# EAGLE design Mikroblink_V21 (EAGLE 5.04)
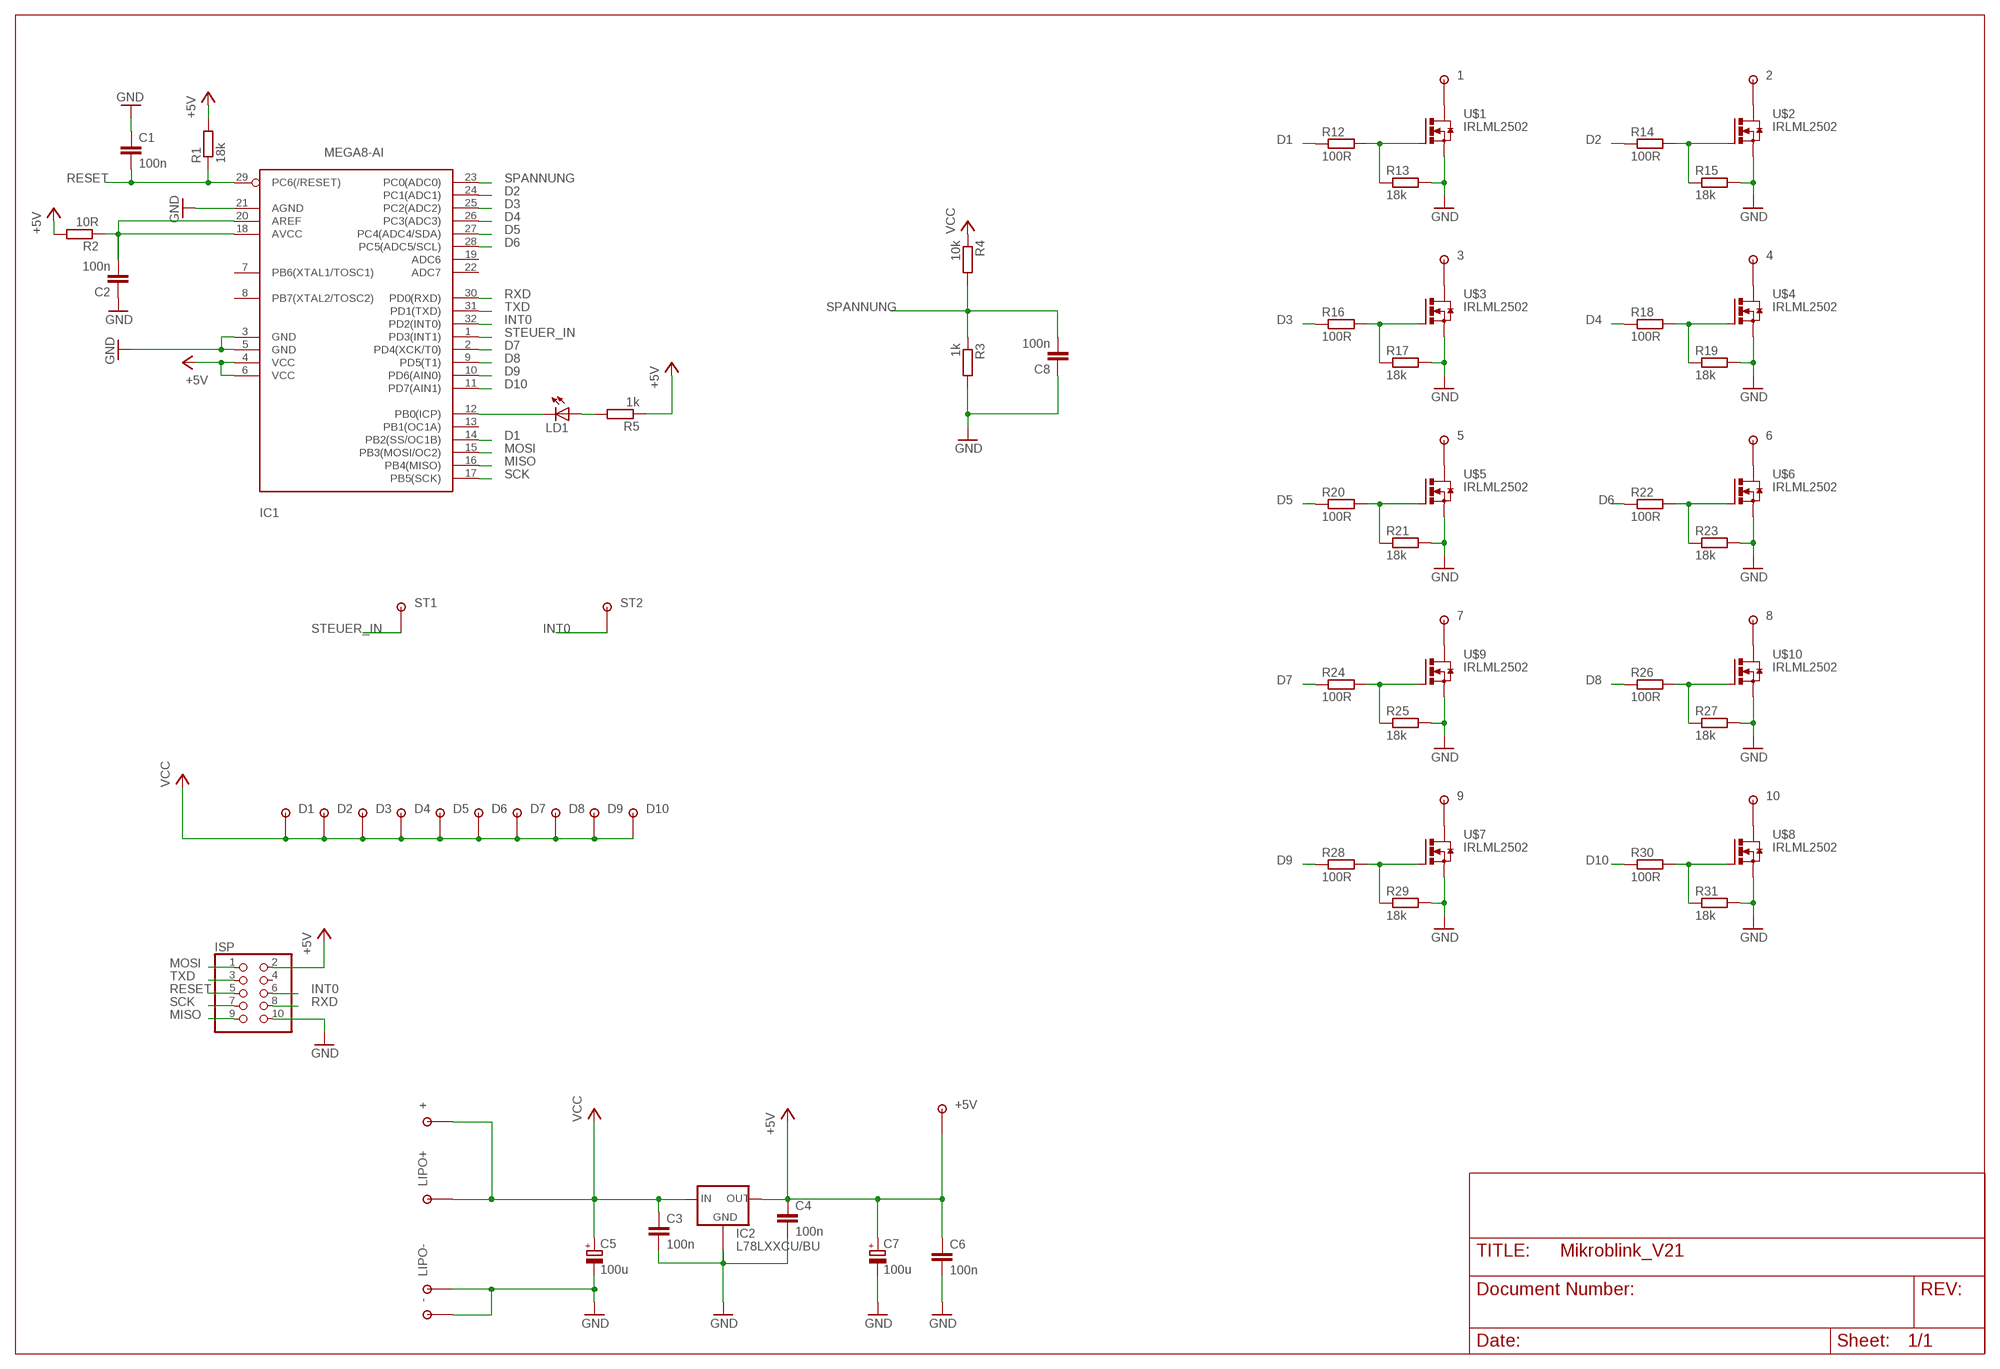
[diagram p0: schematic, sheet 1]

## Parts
1  PAD1  [PAD1]
2  PAD1  [PAD1]
3  PAD1  [PAD1]
4  PAD1  [PAD1]
5  PAD1  [PAD1]
6  PAD1  [PAD1]
7  PAD1  [PAD1]
8  PAD1  [PAD1]
9  PAD1  [PAD1]
10  PAD1  [PAD1]
+  PAD1  [PAD1]
+5V  PAD1  [PAD1]
-  PAD1  [PAD1]
C1  100n  C-EUC0805  [C0805]
C2  100n  C-EUC0805  [C0805]
C3  100n  C-EUC0805  [C0805]
C4  100n  C-EUC0805  [C0805]
C5  100u  CPOL-EU153CLV-0405  [153CLV-0405]
C6  100n  C-EUC0805  [C0805]
C7  100u  CPOL-EU153CLV-0405  [153CLV-0405]
C8  100n  C-EUC0805  [C0805]
D1  PAD1  [PAD1]
D2  PAD1  [PAD1]
D3  PAD1  [PAD1]
D4  PAD1  [PAD1]
D5  PAD1  [PAD1]
D6  PAD1  [PAD1]
D7  PAD1  [PAD1]
D8  PAD1  [PAD1]
D9  PAD1  [PAD1]
D10  PAD1  [PAD1]
IC1  MEGA8-AI  [TQFP32-08]
IC2  L78LXXCU/BU  [SOT89]
ISP  ISP_RAINER  [ISP_RAINER]
LD1  LEDCHIP-LED0805  [CHIP-LED0805]
LIPO+  PAD1  [PAD1]
LIPO-  PAD1  [PAD1]
R1  18k  R-EU_R0805  [R0805]
R2  10R  R-EU_R0805  [R0805]
R3  1k  R-EU_R0805  [R0805]
R4  10k  R-EU_R0805  [R0805]
R5  1k  R-EU_R0805  [R0805]
R12  100R  R-EU_R0805  [R0805]
R13  18k  R-EU_R0805  [R0805]
R14  100R  R-EU_R0805  [R0805]
R15  18k  R-EU_R0805  [R0805]
R16  100R  R-EU_R0805  [R0805]
R17  18k  R-EU_R0805  [R0805]
R18  100R  R-EU_R0805  [R0805]
R19  18k  R-EU_R0805  [R0805]
R20  100R  R-EU_R0805  [R0805]
R21  18k  R-EU_R0805  [R0805]
R22  100R  R-EU_R0805  [R0805]
R23  18k  R-EU_R0805  [R0805]
R24  100R  R-EU_R0805  [R0805]
R25  18k  R-EU_R0805  [R0805]
R26  100R  R-EU_R0805  [R0805]
R27  18k  R-EU_R0805  [R0805]
R28  100R  R-EU_R0805  [R0805]
R29  18k  R-EU_R0805  [R0805]
R30  100R  R-EU_R0805  [R0805]
R31  18k  R-EU_R0805  [R0805]
ST1  PAD1  [PAD1]
ST2  PAD1  [PAD1]
U$1  IRLML2502  [MICRO3]
U$2  IRLML2502  [MICRO3]
U$3  IRLML2502  [MICRO3]
U$4  IRLML2502  [MICRO3]
U$5  IRLML2502  [MICRO3]
U$6  IRLML2502  [MICRO3]
U$7  IRLML2502  [MICRO3]
U$8  IRLML2502  [MICRO3]
U$9  IRLML2502  [MICRO3]
U$10  IRLML2502  [MICRO3]

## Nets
+5V: +5V.P$1(PIN1) C4.1 C6.1 C7.+ IC1.4(VCC) IC1.6(VCC) IC2.1(OUT) ISP.2 R1.2 R2.2 R5.1
AREF_AVCC: C2.2 IC1.18(AVCC) IC1.20(AREF) R2.1
D1: IC1.14(PB2(SS/OC1B)) R12.1
D2: IC1.24(PC1(ADC1)) R14.1
D3: IC1.25(PC2(ADC2)) R16.1
D4: IC1.26(PC3(ADC3)) R18.1
D5: IC1.27(PC4(ADC4/SDA)) R20.1
D6: IC1.28(PC5(ADC5/SCL)) R22.1
D7: IC1.2(PD4(XCK/T0)) R24.1
D8: IC1.9(PD5(T1)) R26.1
D9: IC1.10(PD6(AIN0)) R28.1
D10: IC1.11(PD7(AIN1)) R30.1
GND: -.P$1(PIN1) C1.1 C2.1 C3.2 C4.2 C5.- C6.2 C7.- C8.1 IC1.3(GND) IC1.5(GND) IC1.21(AGND) IC2.4(GND1) ISP.10 LIPO-.P$1(PIN1) R3.2 R13.2 R15.2 R17.2 R19.2 R21.2 R23.2 R25.2 R27.2 R29.2 R31.2 U$1.2(S) U$2.2(S) U$3.2(S) U$4.2(S) U$5.2(S) U$6.2(S) U$7.2(S) U$8.2(S) U$9.2(S) U$10.2(S)
INT0: IC1.32(PD2(INT0)) ISP.6 ST2.P$1(PIN1)
MISO: IC1.16(PB4(MISO)) ISP.9
MOSI: IC1.15(PB3(MOSI/OC2)) ISP.1
N$1: R12.2 R13.1 U$1.1(G)
N$2: R14.2 R15.1 U$2.1(G)
N$3: R16.2 R17.1 U$3.1(G)
N$4: R18.2 R19.1 U$4.1(G)
N$5: R20.2 R21.1 U$5.1(G)
N$6: R22.2 R23.1 U$6.1(G)
N$7: R28.2 R29.1 U$7.1(G)
N$10: IC1.12(PB0(ICP)) LD1.C
N$12: LD1.A R5.2
N$13: R24.2 R25.1 U$9.1(G)
N$14: R26.2 R27.1 U$10.1(G)
N$16: R30.2 R31.1 U$8.1(G)
N$22: 1.P$1(PIN1) U$1.3(D)
N$23: 2.P$1(PIN1) U$2.3(D)
N$24: 3.P$1(PIN1) U$3.3(D)
N$25: 4.P$1(PIN1) U$4.3(D)
N$26: 5.P$1(PIN1) U$5.3(D)
N$27: 6.P$1(PIN1) U$6.3(D)
N$28: 7.P$1(PIN1) U$9.3(D)
N$29: 8.P$1(PIN1) U$10.3(D)
N$30: 9.P$1(PIN1) U$7.3(D)
N$31: 10.P$1(PIN1) U$8.3(D)
RESET: C1.2 IC1.29(PC6(/RESET)) ISP.5 R1.1
RXD: IC1.30(PD0(RXD)) ISP.8
SCK: IC1.17(PB5(SCK)) ISP.7
SPANNUNG: C8.2 IC1.23(PC0(ADC0)) R3.1 R4.2
STEUER_IN: IC1.1(PD3(INT1)) ST1.P$1(PIN1)
TXD: IC1.31(PD1(TXD)) ISP.3
VCC: +.P$1(PIN1) C3.1 C5.+ D1.P$1(PIN1) D2.P$1(PIN1) D3.P$1(PIN1) D4.P$1(PIN1) D5.P$1(PIN1) D6.P$1(PIN1) D7.P$1(PIN1) D8.P$1(PIN1) D9.P$1(PIN1) D10.P$1(PIN1) IC2.3(IN) LIPO+.P$1(PIN1) R4.1
Unconnected: IC1.7(PB6(XTAL1/TOSC1)) IC1.8(PB7(XTAL2/TOSC2)) IC1.13(PB1(OC1A)) IC1.19(ADC6) IC1.22(ADC7) IC2.2(GND) ISP.4

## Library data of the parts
1-10 + +5V - D1-D10 LIPO+ LIPO- ST1 ST2 = Rainer:PAD1
C1-C4 C6 C8 = rcl:C-EU: CAPACITOR, European symbol
C5 C7 = rcl:CPOL-EU: POLARIZED CAPACITOR, European symbol
IC1 = atmel:MEGA8: MICROCONTROLLER 8 Kbytes FLASH, 1 kbytes SRAM, 512 bytes EEPROM, USART, 6-channel 10 bit ADC, 2-channel 8 bit ADC Pin compatible with Atmega48, ATMega88, ATMega168 Source: avr.lbr
IC2 = v-reg:L78LXXCU/BU: VOLTAGE REGULATOR
ISP = pinhead:ISP_RAINER
LD1 = led:LED: LED
R1-R5 R12-R31 = rcl:R-EU_: RESISTOR, European symbol
U$1-U$10 = transistor-power:IRLML2502

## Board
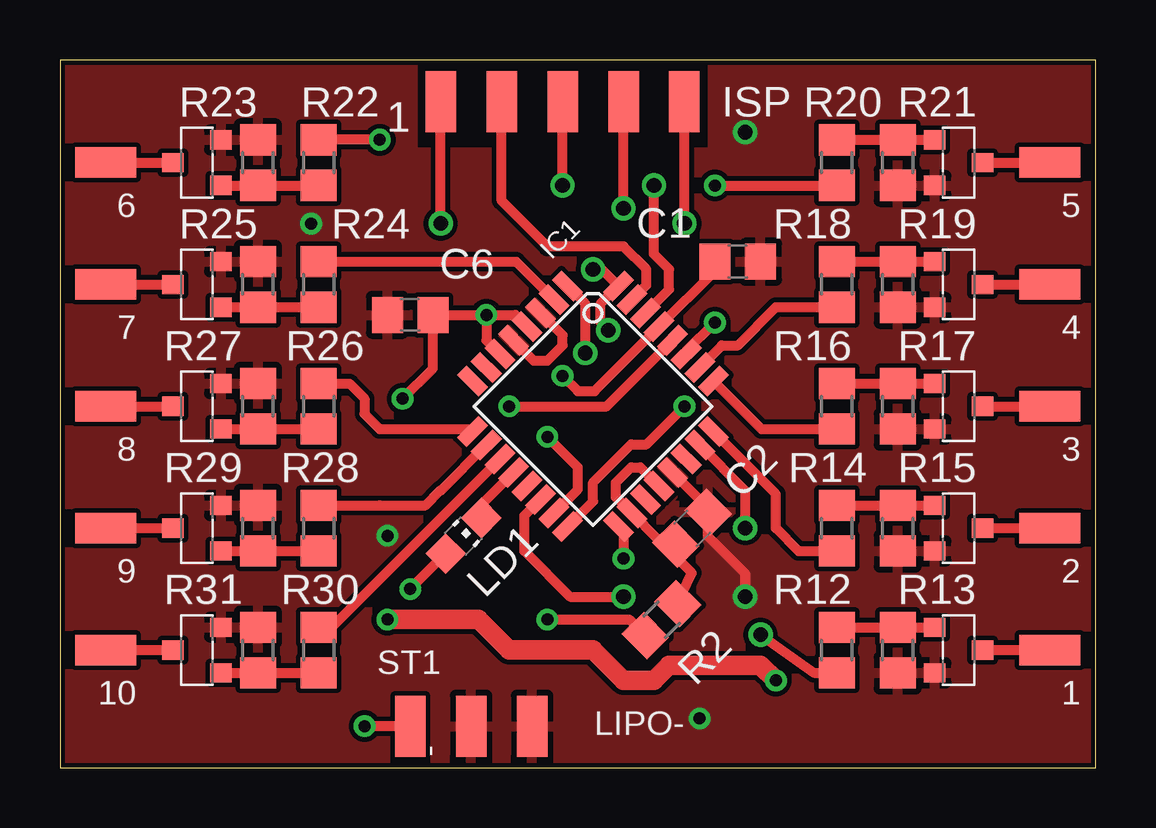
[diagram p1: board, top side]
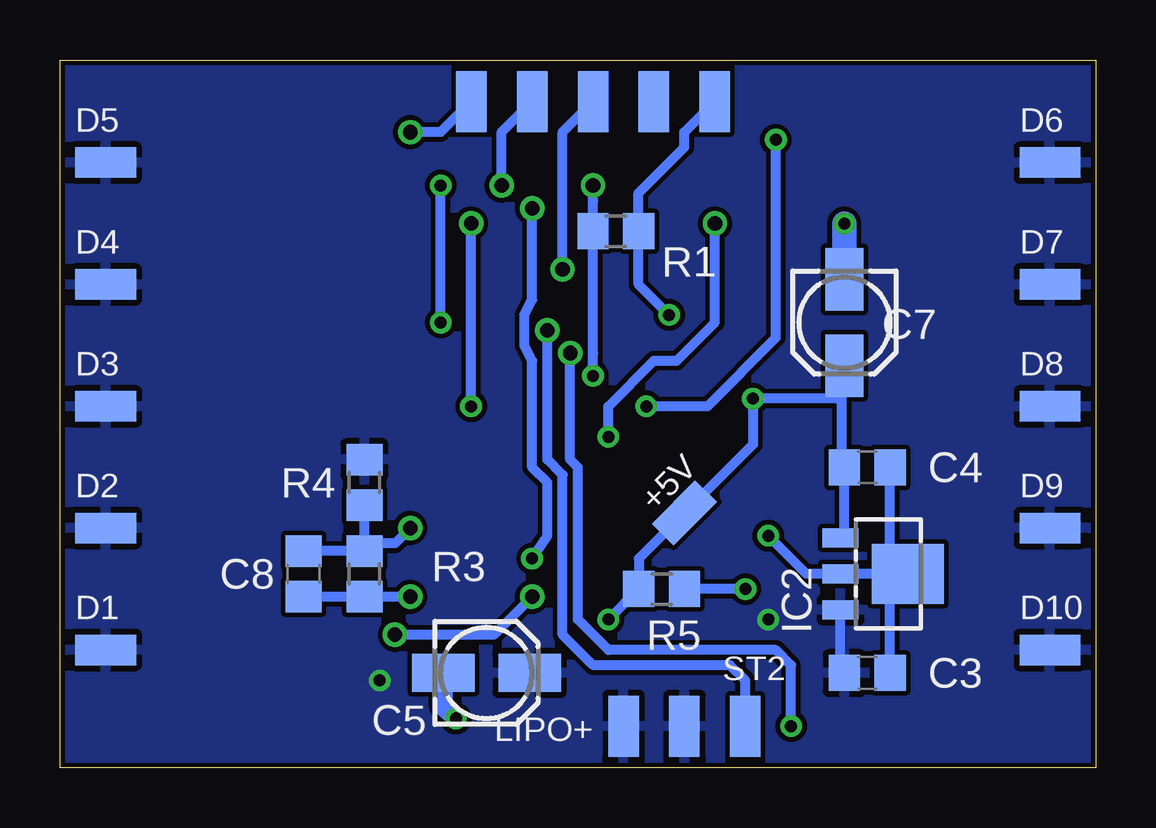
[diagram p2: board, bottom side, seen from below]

Size 43.17 x 29.52 mm. Coordinates in mm from the lower left corner, seen from the top.
Outline: 43.17,0 43.17,29.52 0,29.52 0,0 43.17,0
Copper layers (1*16): Top 0.035mm / dielectric 1.5mm / Bottom 0.035mm
Design rules "ZWILLING": minimum track width 0.2mm, minimum drill 0.5mm, track to track 0.2mm, track to pad 0.2mm, pad to pad 0.2mm, via to via 0.2mm, smd to smd 0mil, copper to edge 0.2mm, drill to drill 0.2mm, minimum pad ring 8mil, minimum via ring 8mil, stop-mask expansion 0.1mm, vias tented up to drill 0mil, thermal gap 10mil
tRestrict: area 14.9,25.9 to 27,29.4; area 17.7,10.6 to 26.7,19.6

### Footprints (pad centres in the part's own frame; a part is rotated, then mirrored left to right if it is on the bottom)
PAD1 = smd 2.54 x 1.27: P$1 0,0
C0805 = smd 1.3 x 1.5: 1 -0.95,0; 2 0.95,0
153CLV-0405 = smd 2.6 x 1.6: + 1.8,0; - -1.8,0
TQFP32-08 = smd 1.27 x 0.559: 1 -4.293,2.8; 2 -4.293,2; 3 -4.293,1.2; 4 -4.293,0.4; 5 -4.293,-0.4; 6 -4.293,-1.2; 7 -4.293,-2; 8 -4.293,-2.8; 17 4.293,-2.8; 18 4.293,-2; 19 4.293,-1.2; 20 4.293,-0.4; 21 4.293,0.4; 22 4.293,1.2; 23 4.293,2; 24 4.293,2.8 | smd 0.559 x 1.27: 9 -2.8,-4.293; 10 -2,-4.293; 11 -1.2,-4.293; 12 -0.4,-4.293; 13 0.4,-4.293; 14 1.2,-4.293; 15 2,-4.293; 16 2.8,-4.293; 25 2.8,4.293; 26 2,4.293; 27 1.2,4.293; 28 0.4,4.293; 29 -0.4,4.293; 30 -1.2,4.293; 31 -2,4.293; 32 -2.8,4.293
SOT89 = smd 0.8 x 1.5: 1 -1.5,-1.75; 2 0,-1.75; 3 1.5,-1.75 | smd 2.5 x 3: 4 0,1.05
ISP_RAINER = smd 2.54 x 1.27: 1 0,10.16; 3 0,7.62; 5 0,5.08; 7 0,2.54; 9 0,0 | smd 2.54 x 1.27 bottom: 2 0,10.16; 4 0,7.62; 6 0,5.08; 8 0,2.54; 10 0,0
CHIP-LED0805 = smd 1.2 x 1.2: A 0,-1.05; C 0,1.05
R0805 = smd 1.3 x 1.5: 1 -0.95,0; 2 0.95,0
MICRO3 = smd 0.8 x 0.9: 1 -0.95,-1; 2 0.95,-1; 3 0,1

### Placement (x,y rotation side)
1  41.27,4.92 180 top
2  41.27,10 180 top
3  41.27,15.07 180 top
4  41.27,20.16 180 top
5  41.27,25.23 180 top
6  1.9,25.23 180 top
7  1.9,20.16 180 top
8  1.9,15.07 180 top
9  1.9,10 180 top
10  1.9,4.92 180 top
+  17.14,1.74 270 bottom
+5V  17.14,10.63 225 bottom
-  17.14,1.74 90 top
C1  28.25,21.11 180 top
C2  26.35,10 225 top
C3  9.52,3.96 0 bottom
C4  9.52,12.54 0 bottom
C5  25.39,3.96 0 bottom
C6  14.6,18.89 180 top
C7  10.47,18.57 270 bottom
C8  33.02,8.09 90 bottom
D1  41.27,4.92 0 bottom
D2  41.27,10 0 bottom
D3  41.27,15.07 0 bottom
D4  41.27,20.16 0 bottom
D5  41.27,25.23 0 bottom
D6  1.9,25.23 0 bottom
D7  1.9,20.16 0 bottom
D8  1.9,15.07 0 bottom
D9  1.9,10 0 bottom
D10  1.9,4.92 0 bottom
IC1  22.22,15.07 315 top
IC2  8.88,8.09 270 bottom
ISP  26.03,27.77 90 top
LD1  16.82,9.68 315 top
LIPO+  19.68,1.74 90 bottom
LIPO-  19.68,1.74 90 top
R1  20,22.38 0 bottom
R2  25.08,6.18 225 top
R3  30.48,8.09 270 bottom
R4  30.48,11.9 270 bottom
R5  18.09,7.45 0 bottom
R12  32.38,4.92 90 top
R13  34.92,4.92 270 top
R14  32.38,10 90 top
R15  34.92,10 270 top
R16  32.38,15.07 90 top
R17  34.92,15.07 270 top
R18  32.38,20.16 90 top
R19  34.92,20.16 270 top
R20  32.38,25.23 90 top
R21  34.92,25.23 270 top
R22  10.79,25.23 270 top
R23  8.25,25.23 90 top
R24  10.79,20.16 270 top
R25  8.25,20.16 90 top
R26  10.79,15.07 270 top
R27  8.25,15.07 90 top
R28  10.79,10 270 top
R29  8.25,10 90 top
R30  10.79,4.92 270 top
R31  8.25,4.92 90 top
ST1  14.6,1.74 90 top
ST2  14.6,1.74 90 bottom
U$1  37.46,4.92 270 top
U$2  37.46,10 270 top
U$3  37.46,15.07 270 top
U$4  37.46,20.16 270 top
U$5  37.46,25.23 270 top
U$6  5.71,25.23 90 top
U$7  5.71,10 90 top
U$8  5.71,4.92 90 top
U$9  5.71,20.16 90 top
U$10  5.71,15.07 90 top

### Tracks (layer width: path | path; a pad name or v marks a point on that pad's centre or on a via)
+5V  (via drill 0.5)
  Top 0.406: v17.78,18.89 C6.1 15.55,16.66 v14.28,15.39 | IC1.4 18.98,18.89 v17.78,18.89 | IC1.6 17.78,17.82 v17.78,18.89 | v20.32,6.18 23.73,6.18 R2.2
  Bottom 0.406: v17.78,18.89 19.05,20.16 R1.2 19.05,23.96 17.14,25.87 17.14,26.5 ISP.2 | 10.58,15.39 v14.28,15.39 14.28,13.49 +5V.P$1 19.04,8.73 R5.1 v20.32,6.18 | 10.58,15.39 C7.+ | 10.58,15.39 10.58,12.64 C4.1 10.47,9.75 IC2.1
AREF_AVCC
  Top 0.406: C2.2 25.14,9.32 24.93,9.53 | 24.93,9.53 IC1.18 23.17,11.29 23.17,11.9 23.81,12.54 24.19,12.54 IC1.20 | R2.1 26.34,8.13 24.93,9.53
D1  (via drill 0.61)
  Top 0.406: IC1.14 19.36,10.52 19.36,9.04 21.27,7.14 v23.49,7.14 | R12.1 31.43,3.96 v29.21,5.55
  Bottom 0.406: v29.21,5.55 25.08,5.55 v23.49,7.14
D2
  Top 0.406: R14.1 30.79,9.04 29.84,10 29.84,11.41 IC1.24
D3
  Top 0.406: IC1.25 29.24,14.12 R16.1
D4
  Top 0.406: 31.72,19.21 R18.1 29.84,19.21 28.25,17.62 27.59,17.62 IC1.26
D5  (via drill 0.5)
  Top 0.406: R20.1 v27.3,24.28 | v27.3,18.57 26.1,17.37 IC1.27
  Bottom 0.406: v27.3,18.57 v27.3,24.28
D6  (via drill 0.5)
  Top 0.406: R22.1 v13.33,26.19 | v18.73,15.07 22.79,15.07 IC1.28
  Bottom 0.406: v13.33,26.19 13.33,17.93 16.19,15.07 v18.73,15.07
D7
  Top 0.406: R24.1 19.02,21.11 IC1.2
D8
  Top 0.406: R26.1 12.06,16.03 12.69,15.39 12.69,14.76 13.33,14.12 17.1,14.12 IC1.9
D9
  Top 0.406: IC1.10 15.9,11.58 15.87,11.58 15.23,10.95 13.33,10.95 R28.1
D10
  Top 0.406: IC1.11 11.31,5.86 R30.1
GND  (via drill 0.5, 0.61)
  Top 0.406: IC1.21 27.02,10.84 C2.1 27.02,9.64 28.57,8.09 v28.57,7.14 | IC1.3 20.95,18.04 20.95,17.62 20.32,16.98 19.75,16.98 IC1.5
  Bottom 0.406: C4.2 8.57,8.82 8.36,8.61 | 8.36,8.61 IC2.4 12.06,8.09 v13.65,9.68 | C3.2 8.57,8.09 | 8.57,8.09 10.79,8.09 | 8.57,8.09 8.36,8.09 8.36,8.61 | C8.1 R3.2 v28.57,7.14 | v28.57,26.5 27.3,26.5 ISP.10
  Bottom 0.813: v26.67,2.06 27.2,2.59 C5.-
  Bottom 1.016: C7.- v10.47,22.7
  pour Top: -0.01,29.68 43.17,29.68 43.17,-0.17 -0.01,-0.17
INT0  (via drill 0.61)
  Top 0.406: v22.22,20.79 22.58,20.79 IC1.32 22.54,19.35 22.54,18.57 v22.86,18.25
  Bottom 0.406: v22.86,18.25 22.86,12.85 22.22,12.22 22.22,5.55 20.95,4.28 15.23,4.28 14.6,3.65 ST2.P$1 | ISP.6 22.22,26.5 v22.22,20.79
MISO  (via drill 0.5, 0.61)
  Top 0.406: v26.03,22.7 ISP.9 | 26.03,14.93 v26.03,15.07 24.44,13.49 23.81,13.49 22.22,11.9 22.22,11.11 IC1.16
  Bottom 0.406: v26.03,15.07 v26.03,22.7
MOSI  (via drill 0.5, 0.61)
  Top 0.406: v15.87,22.7 ISP.1 | v20.32,13.8 21.59,12.54 21.59,11.61 IC1.15
  Bottom 0.406: v15.87,22.7 15.87,18.57 17.46,16.98 18.41,16.98 20.32,15.07 v20.32,13.8
N$1
  Top 0.406: U$1.1 R13.1 R12.2
N$2
  Top 0.406: U$2.1 R15.1 R14.2
N$3
  Top 0.406: R16.2 R17.1 U$3.1
N$4
  Top 0.406: U$4.1 R19.1 R18.2
N$5
  Top 0.406: U$5.1 R21.1 R20.2
N$6
  Top 0.406: R22.2 R23.1 U$6.1
N$7
  Top 0.406: R28.2 R29.1 U$7.1
N$10
  Top 0.406: IC1.12 17.32,10.74 LD1.C
N$12  (via drill 0.5)
  Top 0.406: v14.6,7.45 LD1.A
  Bottom 0.406: v14.6,7.45 R5.2
N$13
  Top 0.406: R24.2 R25.1 U$9.1
N$14
  Top 0.406: R26.2 R27.1 U$10.1
N$16
  Top 0.406: U$8.1 R31.1 R30.2
N$22
  Top 0.406: U$1.3 1.P$1
N$23
  Top 0.406: U$2.3 2.P$1
N$24
  Top 0.406: U$3.3 3.P$1
N$25
  Top 0.406: U$4.3 4.P$1
N$26
  Top 0.406: U$5.3 5.P$1
N$27
  Top 0.406: 6.P$1 U$6.3
N$28
  Top 0.406: 7.P$1 U$9.3
N$29
  Top 0.406: 8.P$1 U$10.3
N$30
  Top 0.406: 9.P$1 U$7.3
N$31
  Top 0.406: 10.P$1 U$8.3
RESET  (via drill 0.5, 0.61)
  Top 0.406: v20.95,24.28 ISP.5 | v20.95,16.34 21.59,15.71 22.29,15.71 IC1.29 27.3,20.72 C1.2
  Bottom 0.406: R1.1 20.95,23.64 | v20.95,16.34 20.95,17.3 R1.1 | R1.1 20.95,23.65 v20.95,24.28
RXD  (via drill 0.61)
  Top 0.406: v24.76,24.28 24.76,21.43 25.39,20.79 25.39,19.95 IC1.30
  Bottom 0.406: ISP.8 24.76,26.5 v24.76,24.28
SCK  (via drill 0.5, 0.61)
  Top 0.406: IC1.17 23.49,9.84 v23.49,8.73 | v23.49,23.33 ISP.7
  Bottom 0.406: v23.49,23.33 23.49,19.52 23.81,18.89 23.81,17.62 23.49,16.98 23.49,12.54 22.86,11.9 22.86,9.68 v23.49,8.73
SPANNUNG  (via drill 0.61)
  Top 0.406: IC1.23 28.57,11.55 v28.57,10
  Bottom 0.406: R3.1 30.16,9.36 29.21,9.36 v28.57,10 | R3.1 C8.2 | R3.1 R4.2
STEUER_IN  (via drill 0.5, 0.61)
  Top 0.406: ST1.P$1 v12.69,1.74 | IC1.1 21.9,19.35 v21.9,17.3
  Bottom 0.406: v21.9,17.3 21.9,12.85 21.59,12.54 21.59,6.18 20.32,4.92 13.33,4.92 12.69,4.28 v12.69,1.74
TXD
  Top 0.406: ISP.3 18.41,23.65 20.32,21.74 23.49,21.74 24.44,20.79 24.44,20.13 IC1.31
VCC  (via drill 0.5)
  Top 0.813: v29.84,3.65 29.21,4.28 25.39,4.28 24.76,3.65 23.49,3.65 22.22,4.92 18.73,4.92 17.46,6.18 v13.65,6.18
  Bottom 0.406: IC2.3 10.63,4.13 C3.1 10.79,3.65
  Bottom 0.813: C5.+ 23.49,3.86
  pour Bottom: -0.01,29.68 43.17,29.68 43.17,-0.17 -0.01,-0.17

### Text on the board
bStop: R.B. 01-2009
